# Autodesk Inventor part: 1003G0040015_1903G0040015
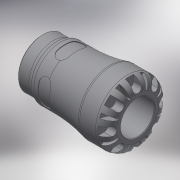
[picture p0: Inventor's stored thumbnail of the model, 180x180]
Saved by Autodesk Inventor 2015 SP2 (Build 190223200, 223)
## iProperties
Created: 2016-12
Part Number: 1003G0040015_1903G0040015
Material: Generic
Description: PLASSON FEMALE ADAPTOR 40X1 1/2" SERIES 1
Document SubType Name: Modeling
Designer: KIM
Mass: 664.223 g
Surface Area: 733.008 cm^2
Volume: 474.445 cm^3
Density: 1 g/cm^3
Appearance: Default
Author: KIM
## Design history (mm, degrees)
derived "1003G.ipt"
feature "Solid1::1003G.ipt"
tag "TaggingFeature1"
body "Solid1"
other parameters: "d0" = 103, "d1" = 29.4, "d8" = 59.5, "d13" = 8, "d14" = 8, "d15" = 0, "d17" = 360 deg, "d19" = 8 deg, "d20" = 0.8, "d21" = 0.8, "d22" = 8 deg, "d24" = 0, "d26" = 360 deg, "d32" = 7, "d33" = 7, "d39" = 1.34535, "d42" = 44.845, "d43" = 54.6, "d46" = 3.33333, "d47" = 19, "d48" = 42.60275, "d50" = 4.62, "d51" = 0.7, "d54" = 14, "d55" = 8.8, "d57" = 15.68, "d58" = 0, "d68" = 360 deg, "d72" = 0.8, "d74" = 0, "d76" = 11.9, "H_" = 103, "G_" = 44.845, "l_2" = 19, "d9" = 10, "d49" = 14
